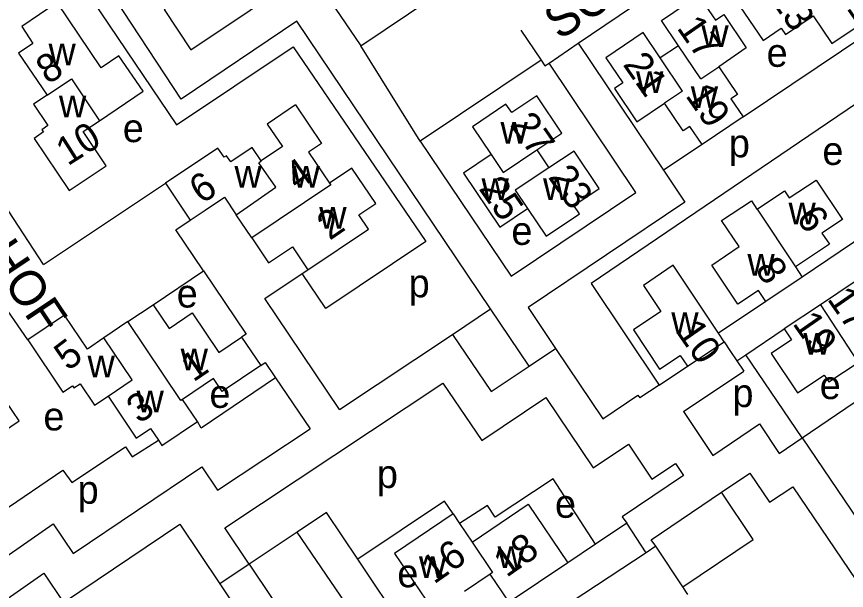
# Model space of a CAD drawing. Extents: x 158356 to 159894, y 383831 to 385260.
# Drawn here: x 158947.4 to 159064.9, y 384584.4 to 384665.6 of the extents above; entities that cross this region are included whole.
import ezdxf

# ---------------------------------------------------------------- set-up
doc = ezdxf.new("R2010")
doc.units = 0
for name, color, linetype in [('BLT_Basislijn', 7, 'Continuous'), ('BLT_Bebouwing', 7, 'Continuous'), ('BLT_Centroide', 7, 'Continuous'), ('BLT_Huisnummer', 7, 'Continuous'), ('BLT_Onderverdeling_panden', 7, 'Continuous'), ('BLT_Straatnaam', 7, 'Continuous')]:
    doc.layers.add(name, color=color, linetype=linetype)

msp = doc.modelspace()

# ---------------------------------------------------------------- linework, layer by layer
at = {"layer": 'BLT_Basislijn'}
for p, q in [((159026.92, 384661.87), (159063.28, 384686.59)), ((158996.11, 384661.51), (159012.69, 384672.67)), ((159050.27, 384651.45), (159075.41, 384668.36)), ((159014.5, 384624.26), (158987.07, 384664.99)), ((159018.76, 384663.73), (159021.64, 384659.49)), ((159004.53, 384648.01), (158996.11, 384661.51)), ((159022.78, 384659.06), (159026.92, 384661.87)), ((159026.92, 384661.87), (159038.98, 384643.87)), ((159021.64, 384659.49), (159004.53, 384648.01)), ((159021.64, 384659.49), (159022.2, 384658.67)), ((159022.2, 384658.67), (159022.78, 384659.06)), ((159074.64, 384658.99), (159028.73, 384627.82)), ((159044.45, 384647.53), (159038.98, 384643.87)), ((158951.18, 384630.53), (158968.46, 384642.04)), ((159072.82, 384638.35), (159058.63, 384628.73)), ((158948.96, 384619.87), (158941.9, 384630.1)), ((158966.71, 384624.83), (158973.83, 384629.65)), ((158987.84, 384629.27), (158988.62, 384629.78)), ((159028.73, 384627.82), (159038.37, 384613.43)), ((159053.47, 384625.29), (159046.76, 384620.8)), ((159009.11, 384620.63), (159014.5, 384624.26)), ((159019.98, 384616.13), (159014.5, 384624.26)), ((159050.63, 384617.74), (159056.09, 384621.4)), ((158993.09, 384610), (159009.11, 384620.63)), ((159047.58, 384619.57), (159048.49, 384618.21)), ((159019.98, 384616.13), (159023.71, 384618.64)), ((159049.37, 384616.9), (159050.63, 384617.74)), ((159058.64, 384605.97), (159050.63, 384617.74)), ((159049.37, 384616.9), (159050.38, 384615.4)), ((159038.37, 384613.43), (159042.39, 384616.1)), ((159041.81, 384609.71), (159050.38, 384615.4)), ((158984.06, 384614.47), (158988.93, 384607.24)), ((159038.37, 384613.43), (159035.64, 384611.62)), ((159041.81, 384609.71), (159045.95, 384603.45)), ((159051.7, 384591.58), (159047.22, 384598.27)), ((159033.79, 384593.87), (159029.37, 384590.9)), ((159036.53, 384589.7), (159033.79, 384593.87)), ((159000.31, 384573.31), (158987.1, 384592.61)), ((159041.73, 384584.86), (159051.7, 384591.58)), ((159036.53, 384589.7), (159019.79, 384578.68)), ((159037.88, 384590.61), (159036.53, 384589.7)), ((159041.73, 384584.86), (159037.88, 384590.61)), ((158980.31, 384588.06), (158976.16, 384585.28)), ((158976.16, 384585.28), (158980.66, 384578.56)), ((159042.45, 384583.79), (159041.73, 384584.86))]:
    msp.add_line(p, q, dxfattribs=at)
for points in [[(158987.07, 384664.99), (158970.67, 384653.94), (158938.87, 384702.29)], [(158931.35, 384679.05), (158928.31, 384683.75), (158941.46, 384692.58), (158970.04, 384650.29), (158986.56, 384661.35), (159005.35, 384633.8), (158991.18, 384624.3), (158987.84, 384629.27)], [(158969.58, 384667.49), (158968.3, 384666.65), (158972.07, 384660.92), (158988.88, 384672.24), (158996.11, 384661.51)], [(159004.53, 384648.01), (159017.43, 384628.86), (159035.07, 384640.74), (159022.78, 384659.06)], [(158951.18, 384630.53), (158936.87, 384652.41), (158939.93, 384654.42)], [(159038.98, 384643.87), (159042, 384639.38), (159019.82, 384624.44), (159023.71, 384618.64)], [(158973.83, 384629.65), (158969.92, 384635.42), (158971.97, 384636.8)], [(158973.83, 384629.65), (158979.88, 384620.66), (158979.25, 384620.23)], [(158993.09, 384610), (158982.53, 384625.69), (158987.84, 384629.27)], [(159058.64, 384605.97), (159078.23, 384619.28), (159072.66, 384627.45)], [(159009.11, 384620.63), (159014.59, 384612.52), (159019.98, 384616.13)], [(159023.71, 384618.64), (159030.39, 384608.67), (159035.37, 384612.01), (159035.64, 384611.62)], [(159048.49, 384618.21), (159049.37, 384616.9)], [(158981.95, 384616.23), (158982.58, 384616.66), (158984.06, 384614.47)], [(158984.06, 384614.47), (158973.54, 384607.36), (158973, 384608.28)], [(158980.31, 384588.06), (158976.85, 384593.23), (159007.74, 384613.72), (159013.24, 384605.6), (159022.34, 384611.7), (159029.02, 384601.74), (159034.01, 384605.08), (159037.34, 384600.13), (159040.69, 384602.34), (159041.8, 384600.65)], [(158936.45, 384582.58), (158952.55, 384593.8), (158955.38, 384589.59), (158973.61, 384601.84), (158975.82, 384598.55), (158988.93, 384607.24)], [(159045.95, 384603.45), (159052.57, 384607.93), (159055.36, 384603.77), (159058.64, 384605.97)], [(159058.64, 384605.97), (159071.51, 384586.94), (159076.46, 384590.29), (159080.38, 384584.5), (159082.55, 384585.94)], [(158931.67, 384589.7), (158943.52, 384597.61), (158945.18, 384595.44), (158953.94, 384601.41), (158955.19, 384599.65), (158962.79, 384604.68), (158963.77, 384603.26), (158967.47, 384605.62)], [(159023.38, 384600.18), (159015.16, 384594.72), (159014.06, 384596.38), (159010.12, 384593.82)], [(159029.37, 384590.9), (159023.38, 384600.18)], [(159041.8, 384600.65), (159033.12, 384594.77), (159033.79, 384593.87)], [(159047.22, 384598.27), (159051.21, 384600.98), (159053.99, 384596.84), (159057.29, 384599.05), (159070.17, 384580), (159075.12, 384583.35), (159079.03, 384577.58)], [(159037.88, 384590.61), (159037.26, 384591.54), (159047.22, 384598.27)], [(159009.21, 384595.2), (159007.99, 384597.01), (158995.68, 384588.8)], [(158995.68, 384588.8), (158991.26, 384595.4), (158987.1, 384592.61)], [(158939.24, 384578.42), (158951.24, 384586.79), (158954.02, 384582.66), (158970.5, 384593.72), (158976.16, 384585.28)], [(158987.1, 384592.61), (158980.31, 384588.06)], [(159029.37, 384590.9), (159025.43, 384588.26)], [(159002.28, 384578.96), (158995.68, 384588.8)], [(158980.31, 384588.06), (158993.06, 384569.04), (158988.93, 384566.25)]]:
    msp.add_lwpolyline(points, dxfattribs=at)
at = {"layer": 'BLT_Bebouwing'}
for p, q in [((159041.11, 384661.51), (159038.5, 384659.82)), ((159050.27, 384651.45), (159044.45, 384647.53)), ((159021.05, 384646.75), (159022.76, 384644.21)), ((158968.46, 384642.04), (158971.97, 384636.8)), ((158971.97, 384636.8), (158974.08, 384638.23)), ((158980.68, 384634.28), (158978.46, 384637.58)), ((158963.15, 384622.43), (158966.71, 384624.83)), ((158954.16, 384623.37), (158948.96, 384619.87)), ((158963.15, 384622.43), (158959.74, 384620.12)), ((158979.25, 384620.23), (158981.95, 384616.23)), ((159042.39, 384616.1), (159047.58, 384619.57)), ((158973, 384608.28), (158970.88, 384611.42)), ((159009.21, 384595.2), (159010.12, 384593.82)), ((159010.12, 384593.82), (159011.87, 384591.2)), ((159014.46, 384586.66), (159010.81, 384584.21))]:
    msp.add_line(p, q, dxfattribs=at)
for points in [[(159054.98, 384673.45), (159051.05, 384670.79), (159051.68, 384669.85), (159049.12, 384668.12), (159053.08, 384662.27), (159055.64, 384663.99), (159056.25, 384663.09), (159060.17, 384665.76)], [(159060.17, 384665.76), (159062.8, 384661.83), (159067.53, 384664.99), (159066.73, 384666.19), (159070.3, 384668.57), (159066.71, 384673.91), (159063.17, 384671.53)], [(159041.11, 384661.51), (159038.68, 384665.09), (159043.95, 384668.66), (159046.33, 384665.14), (159047.52, 384665.95), (159050.71, 384661.2), (159046.8, 384658.55)], [(158959.11, 384650.9), (158965.29, 384655.07), (158961.88, 384660.11), (158959.37, 384658.41), (158953.14, 384667.64), (158948.11, 384664.22), (158949.7, 384661.83), (158947.67, 384660.47), (158951.69, 384654.53)], [(159038.5, 384659.82), (159036.11, 384663.38), (159030.82, 384659.82), (159033.21, 384656.25), (159032.04, 384655.46), (159035.22, 384650.75), (159039.14, 384653.38)], [(159046.8, 384658.55), (159049.45, 384654.62), (159048.54, 384654.01), (159050.27, 384651.45)], [(158951.69, 384654.53), (158949.79, 384653.25), (158951.82, 384650.22), (158950.95, 384649.62), (158951.17, 384649.3), (158949.85, 384648.39), (158954.83, 384640.99), (158960.07, 384644.51), (158956.82, 384649.35), (158959.11, 384650.9)], [(159021.05, 384646.75), (159024.61, 384649.15), (159021.05, 384654.43), (159017.49, 384652.05), (159016.68, 384653.22), (159011.93, 384650.04), (159014.57, 384646.12)], [(158986.86, 384653.14), (158982.86, 384650.42), (158985.04, 384647.22), (158982.01, 384645.19)], [(158986.86, 384653.14), (158990.56, 384647.69), (158988.73, 384646.45), (158991.7, 384642.06)], [(159044.45, 384647.53), (159042.72, 384650.09), (159041.79, 384649.46), (159039.14, 384653.38)], [(158982.01, 384645.19), (158980.72, 384647.1), (158977.7, 384645.06), (158977.11, 384645.93), (158976.77, 384645.71), (158975.88, 384647.03), (158968.46, 384642.04)], [(159014.57, 384646.12), (159010.65, 384643.48), (159015.8, 384635.82), (159019.72, 384638.46)], [(159019.72, 384638.46), (159022.36, 384634.53), (159027.1, 384637.72), (159026.31, 384638.9), (159029.88, 384641.3), (159026.34, 384646.58), (159022.76, 384644.21)], [(158988.62, 384629.78), (158997.22, 384635.51), (158995.84, 384637.55), (158998.24, 384639.18), (158994.84, 384644.19), (158991.7, 384642.06)], [(159052.24, 384638.37), (159056.12, 384640.94), (159056.78, 384639.96), (159060.59, 384642.49), (159064.35, 384636.91), (159061.42, 384634.96), (159062.47, 384633.39), (159057.66, 384630.18)], [(158974.08, 384638.23), (158976.8, 384640.05), (158978.46, 384637.58)], [(159053.47, 384625.29), (159052.43, 384626.82), (159049.52, 384624.9), (159045.83, 384630.45), (159049.7, 384633.06), (159047.19, 384636.77), (159051.45, 384639.53), (159052.22, 384638.35), (159052.24, 384638.37)], [(158980.68, 384634.28), (158983.04, 384630.76), (158986.43, 384633.04), (158988.62, 384629.78)], [(159046.76, 384620.8), (159040.37, 384630.41), (159036.15, 384627.57), (159038.62, 384623.87), (159034.72, 384621.25), (159038.43, 384615.7), (159041.34, 384617.62), (159042.39, 384616.1)], [(159057.66, 384630.18), (159058.63, 384628.73)], [(159058.63, 384628.73), (159053.47, 384625.29)], [(159066.12, 384628.11), (159061.21, 384624.82)], [(158966.71, 384624.83), (158968.98, 384621.47), (158972.24, 384623.67), (158976.04, 384618.07), (158979.25, 384620.23)], [(159061.21, 384624.82), (159056.09, 384621.4)], [(158959.74, 384620.12), (158957.42, 384618.55), (158954.16, 384623.37)], [(159056.09, 384621.4), (159057.11, 384619.86), (159054.21, 384617.9), (159057.95, 384612.35), (159061.73, 384614.87), (159062.42, 384613.9), (159066.54, 384616.66)], [(159047.58, 384619.57), (159046.76, 384620.8)], [(158948.96, 384619.87), (158953.95, 384612.45), (158955.29, 384613.36), (158955.51, 384613.03), (158956.38, 384613.62), (158958.43, 384610.58), (158960.33, 384611.86)], [(158981.95, 384616.23), (158976.51, 384612.55), (158975.27, 384614.38), (158970.88, 384611.42)], [(158938.7, 384604.89), (158941.9, 384607.06), (158943.14, 384605.24), (158947.76, 384608.37), (158945.06, 384612.36), (158941.86, 384610.18), (158939.81, 384613.24)], [(158960.33, 384611.86), (158964.32, 384605.91), (158966.35, 384607.28), (158967.47, 384605.62)], [(158967.47, 384605.62), (158967.96, 384604.89), (158973, 384608.28)], [(159011.87, 384591.2), (159019.83, 384596.56), (159025.43, 384588.26)], [(159009.21, 384595.2), (159000.89, 384589.6), (159006.26, 384581.63)], [(159025.43, 384588.26), (159017.11, 384582.67)], [(159017.11, 384582.67), (159014.46, 384586.66)]]:
    msp.add_lwpolyline(points, dxfattribs=at)
at = {"layer": 'BLT_Onderverdeling_panden'}
for p, q in [((159044.27, 384656.85), (159041.11, 384661.51)), ((159041.68, 384655.09), (159038.5, 384659.82)), ((159044.27, 384656.85), (159046.8, 384658.55)), ((159041.68, 384655.09), (159039.14, 384653.38)), ((159052.24, 384638.37), (159057.66, 384630.18))]:
    msp.add_line(p, q, dxfattribs=at)
for points in [[(158951.69, 384654.53), (158955.15, 384656.84), (158959.11, 384650.9)], [(159014.57, 384646.12), (159016.3, 384643.55), (159021.05, 384646.75)], [(158978.46, 384637.58), (158984.08, 384641.46), (158981.68, 384644.94), (158982.01, 384645.19)], [(159022.76, 384644.21), (159017.99, 384641.04), (159019.72, 384638.46)], [(158991.7, 384642.06), (158991.87, 384641.81), (158980.68, 384634.28)], [(159061.21, 384624.82), (159061.21, 384624.82), (159066.54, 384616.66)], [(158970.88, 384611.42), (158970.65, 384611.27), (158963.15, 384622.43)], [(158960.33, 384611.86), (158963.76, 384614.18), (158959.74, 384620.12)], [(159011.87, 384591.2), (159014.77, 384586.87), (159014.46, 384586.66)]]:
    msp.add_lwpolyline(points, dxfattribs=at)

# ---------------------------------------------------------------- texts
at = {"layer": 'BLT_Centroide'}
for s, p in [('w', (159044.35, 384661.34)), ('w', (158951.9, 384658.76)), ('e', (159053.59, 384658.53)), ('w', (159035.1, 384654.8)), ('w', (159042.85, 384652.69)), ('w', (158953.38, 384651.36)), ('e', (158962.42, 384647.86)), ('w', (159015.9, 384647.65)), ('p', (159048.24, 384645.71)), ('e', (159061.49, 384644.63)), ('w', (158978.23, 384641.43)), ('w', (158986.46, 384641.43)), ('w', (159013.22, 384639.65)), ('w', (159021.93, 384639.65)), ('w', (159056.69, 384636.23)), ('w', (158990.24, 384635.58)), ('e', (159017.45, 384633.3)), ('w', (159050.87, 384628.94)), ('p', (159002.9, 384625.88)), ('e', (158970.06, 384624.43)), ('w', (159040.09, 384620.67)), ('w', (159058.81, 384617.74)), ('w', (158970.61, 384615.53)), ('w', (158957.43, 384614.53)), ('e', (159061.11, 384611.46)), ('e', (158974.69, 384610.21)), ('p', (159048.75, 384610.33)), ('w', (158964.37, 384609.58)), ('e', (158951.18, 384607.02)), ('p', (158998.4, 384598.87)), ('p', (158956.03, 384596.63)), ('e', (159023.62, 384594.64)), ('w', (159015.48, 384587.53)), ('w', (159004.36, 384586.09)), ('e', (159001.3, 384584.8))]:
    msp.add_text(s, height=4, dxfattribs=at).set_placement(p)
at = {"layer": 'BLT_Huisnummer'}
for s, rotation, p in [('11', 304.8063, (159063.12, 384669.28)), ('13', 304.8063, (159053.95, 384668.16)), ('17', 304.8063, (159040.78, 384664.05)), ('8', 32.1525, (158951.79, 384655.96)), ('21', 304.8063, (159033.14, 384658.86)), ('19', 304.8063, (159042, 384654.45)), ('27', 304.8063, (159017.16, 384650.35)), ('10', 32.3731, (158954.62, 384644.41)), ('4', 34.9364, (158987.16, 384640.9)), ('6', 34.3904, (158973.61, 384639)), ('23', 304.8063, (159022.56, 384642.91)), ('25', 304.8063, (159012.74, 384641.27)), ('2', 34.5117, (158991.71, 384633.86)), ('6', 304.8063, (159057.66, 384637.12)), ('8', 304.8063, (159051.84, 384629.82)), ('17', 304.8063, (159062.07, 384625.63)), ('19', 304.8063, (159057.17, 384622.16)), ('10', 304.8063, (159040.71, 384620.97)), ('5', 37.5011, (158954.68, 384615.34)), ('1', 34.3446, (158972.41, 384613.79)), ('3', 34.3446, (158964.73, 384607.87)), ('18', 34.9199, (159016.75, 384586.1)), ('16', 34.8867, (159006.48, 384585.16))]:
    msp.add_text(s, height=4, rotation=rotation, dxfattribs=at).set_placement(p)
at = {"layer": 'BLT_Straatnaam'}
for s, rotation, p in [('SCHADUWMASKERSTRAAT', 33.8882, (159024.27, 384662.2)), ('GETTERHOF', 303.8882, (158927.64, 384654.46))]:
    msp.add_text(s, height=5, rotation=rotation, dxfattribs=at).set_placement(p)

doc.saveas('drawing.dxf')
